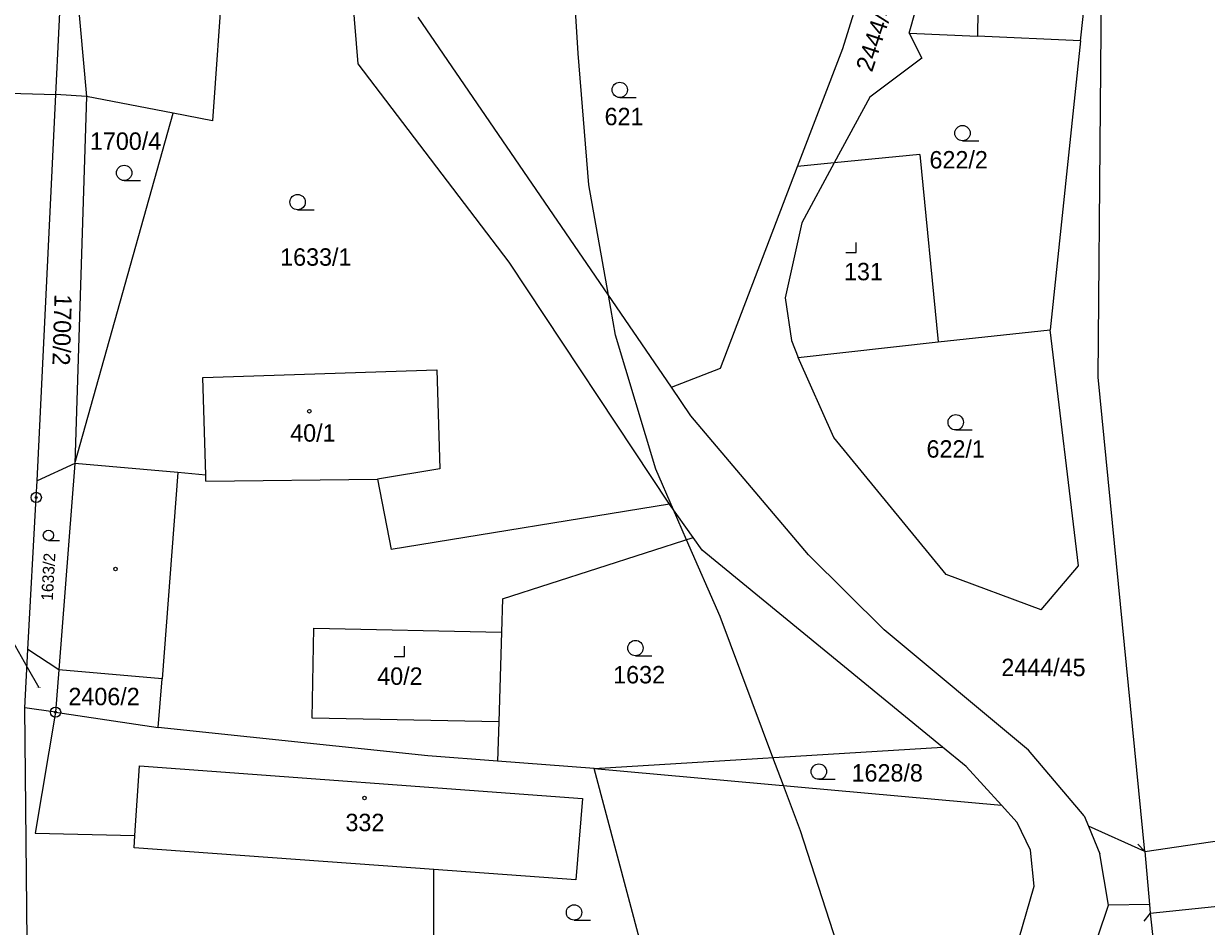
# Model space of a CAD drawing. Extents: x -546762 to -540209, y -1046851 to -1035694.
# Drawn here: x -542720.2 to -542604.8, y -1039556.7 to -1039468.6 of the extents above; entities that cross this region are included whole.
import ezdxf

# ---------------------------------------------------------------- set-up
doc = ezdxf.new("R2010")
doc.units = 0
for name, color, linetype in [('Vrstva 1', 7, 'Continuous'), ('Vrstva 16', 7, 'Continuous'), ('Vrstva 18', 7, 'Continuous'), ('Vrstva 19', 7, 'Continuous'), ('Vrstva 24', 7, 'Continuous'), ('Vrstva 25', 7, 'Continuous'), ('Vrstva 26', 7, 'Continuous'), ('Vrstva 3', 7, 'Continuous'), ('Vrstva 37', 7, 'Continuous'), ('Vrstva 4', 7, 'Continuous'), ('Vrstva 52', 7, 'Continuous')]:
    doc.layers.add(name, color=color, linetype=linetype)

msp = doc.modelspace()

# ---------------------------------------------------------------- linework, layer by layer
at = {"layer": 'Vrstva 1'}
for p, q in [((-542722.87, -1039475.34), (-542717.07, -1039475.49)), ((-542709.35, -1039547.82), (-542708.92, -1039541.01)), ((-542708.92, -1039541.01), (-542665.7, -1039544.19)), ((-542665.7, -1039544.19), (-542666.34, -1039552.15)), ((-542719.1, -1039547.6), (-542709.35, -1039547.82)), ((-542709.43, -1039549), (-542709.35, -1039547.82)), ((-542680.19, -1039551.14), (-542709.43, -1039549)), ((-542666.34, -1039552.15), (-542680.19, -1039551.14)), ((-542680.18, -1039565.65), (-542680.19, -1039551.14))]:
    msp.add_line(p, q, dxfattribs=at)
for points in [[(-542717.07, -1039475.49), (-542715.32, -1039439.55)], [(-542617.09, -1039470.26), (-542614.93, -1039450.36)], [(-542615.38, -1039503.08), (-542614.93, -1039450.36)], [(-542640.3, -1039471), (-542634.14, -1039451.25)], [(-542633.83, -1039469.51), (-542629.48, -1039454.22)], [(-542715.32, -1039461.95), (-542714.08, -1039475.68)], [(-542687.58, -1039472.52), (-542688.45, -1039461.79)], [(-542700.78, -1039463.8), (-542701.79, -1039478.07)], [(-542657.01, -1039504.05), (-542681.72, -1039467.97)], [(-542627.13, -1039467.29), (-542627.16, -1039469.81)], [(-542633.83, -1039469.51), (-542627.16, -1039469.81)], [(-542633.83, -1039469.51), (-542632.58, -1039471.94)], [(-542617.09, -1039470.26), (-542627.16, -1039469.81)], [(-542617.09, -1039470.26), (-542620.05, -1039498.46)], [(-542644.7, -1039482.52), (-542640.3, -1039471)], [(-542672.85, -1039491.86), (-542687.58, -1039472.52)], [(-542632.58, -1039471.94), (-542637.65, -1039475.75)], [(-542718.9, -1039513.21), (-542717.07, -1039475.49)], [(-542714.08, -1039475.68), (-542717.07, -1039475.49)], [(-542714.08, -1039475.68), (-542715.23, -1039511.5)], [(-542705.63, -1039477.32), (-542714.08, -1039475.68)], [(-542637.65, -1039475.75), (-542641.13, -1039482.17)], [(-542715.23, -1039511.5), (-542705.63, -1039477.32)], [(-542701.79, -1039478.07), (-542705.63, -1039477.32)], [(-542632.77, -1039481.35), (-542641.13, -1039482.17)], [(-542632.77, -1039481.35), (-542630.98, -1039499.65)], [(-542652.21, -1039502.21), (-542644.7, -1039482.52)], [(-542641.13, -1039482.17), (-542644.7, -1039482.52)], [(-542641.13, -1039482.17), (-542644.29, -1039488.01)], [(-542644.29, -1039488.01), (-542645.91, -1039495.33)], [(-542657.19, -1039515.49), (-542672.85, -1039491.86)], [(-542645.91, -1039495.33), (-542645.31, -1039499.5)], [(-542630.98, -1039499.65), (-542620.05, -1039498.46)], [(-542617.28, -1039521.5), (-542620.05, -1039498.46)], [(-542645.31, -1039499.5), (-542644.63, -1039501.15)], [(-542644.63, -1039501.15), (-542630.98, -1039499.65)], [(-542641.16, -1039508.96), (-542644.63, -1039501.15)], [(-542702.74, -1039503.11), (-542679.9, -1039502.38)], [(-542679.9, -1039502.38), (-542679.59, -1039512.04)], [(-542657.01, -1039504.05), (-542652.21, -1039502.21)], [(-542702.44, -1039512.64), (-542702.74, -1039503.11)], [(-542610.81, -1039549.38), (-542615.38, -1039503.08)], [(-542655.1, -1039506.86), (-542657.01, -1039504.05)], [(-542643.62, -1039520.41), (-542655.1, -1039506.86)], [(-542630.21, -1039522.33), (-542641.16, -1039508.96)], [(-542715.23, -1039511.5), (-542718.9, -1039513.21)], [(-542715.23, -1039511.5), (-542716.77, -1039531.63)], [(-542705.17, -1039512.4), (-542715.23, -1039511.5)], [(-542702.44, -1039512.64), (-542705.17, -1039512.4)], [(-542679.59, -1039512.04), (-542685.69, -1039513.03)], [(-542718.98, -1039514.82), (-542718.9, -1039513.21)], [(-542685.69, -1039513.03), (-542684.34, -1039519.91)], [(-542719.79, -1039529.65), (-542718.98, -1039514.82)], [(-542657.19, -1039515.49), (-542684.34, -1039519.91)], [(-542654.88, -1039518.74), (-542657.19, -1039515.49)], [(-542673.49, -1039524.73), (-542654.88, -1039518.74)], [(-542654, -1039519.97), (-542654.88, -1039518.74)], [(-542630.56, -1039539.19), (-542654, -1039519.97)], [(-542636.24, -1039527.75), (-542643.62, -1039520.41)], [(-542620.94, -1039525.78), (-542617.28, -1039521.5)], [(-542620.94, -1039525.78), (-542630.21, -1039522.33)], [(-542673.49, -1039524.73), (-542673.59, -1039527.96)], [(-542692.07, -1039536.35), (-542691.89, -1039527.58)], [(-542691.89, -1039527.58), (-542673.59, -1039527.96)], [(-542673.59, -1039527.96), (-542673.86, -1039536.73)], [(-542622.16, -1039539.49), (-542636.24, -1039527.75)], [(-542720.1, -1039535.34), (-542719.79, -1039529.65)], [(-542716.77, -1039531.63), (-542719.79, -1039529.65)], [(-542716.77, -1039531.63), (-542717.09, -1039535.78)], [(-542706.71, -1039532.53), (-542716.77, -1039531.63)], [(-542707.08, -1039537.27), (-542706.71, -1039532.53)], [(-542719.28, -1039616.7), (-542720.1, -1039535.34)], [(-542717.09, -1039535.78), (-542720.1, -1039535.34)], [(-542717.09, -1039535.78), (-542719.1, -1039547.6)], [(-542717.09, -1039535.78), (-542707.08, -1039537.27)], [(-542673.86, -1039536.73), (-542692.07, -1039536.35)], [(-542673.86, -1039536.73), (-542673.98, -1039540.56)], [(-542680.77, -1039540.05), (-542707.08, -1039537.27)], [(-542664.56, -1039541.27), (-542630.56, -1039539.19)], [(-542628.26, -1039541.08), (-542630.56, -1039539.19)], [(-542616.75, -1039545.89), (-542622.16, -1039539.49)], [(-542673.98, -1039540.56), (-542680.77, -1039540.05)], [(-542664.56, -1039541.27), (-542673.98, -1039540.56)], [(-542657.86, -1039566.46), (-542664.56, -1039541.27)], [(-542664.56, -1039541.27), (-542624.82, -1039544.85)], [(-542624.82, -1039544.85), (-542628.26, -1039541.08)], [(-542623.28, -1039546.55), (-542624.82, -1039544.85)], [(-542616.75, -1039545.89), (-542616.33, -1039546.91)], [(-542621.98, -1039549.25), (-542623.28, -1039546.55)], [(-542610.81, -1039549.38), (-542616.33, -1039546.91)], [(-542616.33, -1039546.91), (-542615.21, -1039549.6)], [(-542610.81, -1039549.38), (-542601.31, -1039547.99)], [(-542621.62, -1039552.75), (-542621.98, -1039549.25)], [(-542614.37, -1039554.62), (-542615.21, -1039549.6)], [(-542624.18, -1039561.65), (-542621.62, -1039552.75)], [(-542610.36, -1039554.53), (-542614.37, -1039554.62)], [(-542610.36, -1039554.53), (-542610.29, -1039555.38)], [(-542610.29, -1039555.38), (-542600.59, -1039554.38)], [(-542615.4, -1039557.71), (-542614.37, -1039554.62)], [(-542610.29, -1039555.38), (-542606.95, -1039585.89)]]:
    msp.add_lwpolyline(points, dxfattribs=at)
at = {"layer": 'Vrstva 16'}
msp.add_line((-542719.83, -1039531.42), (-542721.31, -1039528.81), dxfattribs=at)
msp.add_lwpolyline([(-542718.71, -1039533.41), (-542719.83, -1039531.42)], dxfattribs=at)
at = {"layer": 'Vrstva 24'}
for centre, radius in [((-542718.98, -1039514.82), 0.5), ((-542718.98, -1039514.82), 0.1), ((-542717.09, -1039535.78), 0.5), ((-542717.09, -1039535.78), 0.1)]:
    msp.add_circle(centre, radius, dxfattribs=at)
at = {"layer": 'Vrstva 25'}
for p, q in [((-542662.05, -1039475.8), (-542660.45, -1039475.8)), ((-542628.61, -1039480.02), (-542627.01, -1039480.02)), ((-542710.4, -1039483.9), (-542708.8, -1039483.9)), ((-542693.48, -1039486.75), (-542691.88, -1039486.75)), ((-542629.27, -1039508.24), (-542627.67, -1039508.24)), ((-542717.79, -1039519.02), (-542716.72, -1039519.02)), ((-542660.52, -1039530.27), (-542658.92, -1039530.27)), ((-542642.63, -1039542.33), (-542641.03, -1039542.33)), ((-542666.51, -1039556.07), (-542664.91, -1039556.07))]:
    msp.add_line(p, q, dxfattribs=at)
for points in [[(-542639.98, -1039490.93), (-542638.98, -1039490.93), (-542638.98, -1039489.93)], [(-542684.05, -1039530.34), (-542683.05, -1039530.34), (-542683.05, -1039529.34)]]:
    msp.add_lwpolyline(points, dxfattribs=at)
for centre, radius in [((-542662.05, -1039475.05), 0.75), ((-542628.61, -1039479.27), 0.75), ((-542710.4, -1039483.15), 0.75), ((-542693.48, -1039486), 0.75), ((-542692.33, -1039506.41), 0.175), ((-542629.27, -1039507.49), 0.75), ((-542717.79, -1039518.52), 0.503), ((-542711.25, -1039521.8), 0.175), ((-542660.52, -1039529.52), 0.75), ((-542642.63, -1039541.58), 0.75), ((-542686.95, -1039544.15), 0.175), ((-542666.51, -1039555.32), 0.75)]:
    msp.add_circle(centre, radius, dxfattribs=at)
at = {"layer": 'Vrstva 26'}
for p, q in [((-542610.81, -1039549.38), (-542611.51, -1039548.66)), ((-542610.29, -1039555.38), (-542610.92, -1039556.16))]:
    msp.add_line(p, q, dxfattribs=at)
at = {"layer": 'Vrstva 3'}
for points in [[(-542702.74, -1039503.11), (-542679.9, -1039502.38)], [(-542679.9, -1039502.38), (-542679.59, -1039512.04)], [(-542702.44, -1039512.64), (-542702.74, -1039503.11)], [(-542702.42, -1039513.23), (-542702.44, -1039512.64)], [(-542679.59, -1039512.04), (-542685.69, -1039513.03)], [(-542702.42, -1039513.23), (-542685.69, -1039513.03)], [(-542709.35, -1039547.82), (-542708.92, -1039541.01)], [(-542708.92, -1039541.01), (-542665.7, -1039544.19)], [(-542665.7, -1039544.19), (-542666.34, -1039552.15)], [(-542709.43, -1039549), (-542709.35, -1039547.82)], [(-542680.19, -1039551.14), (-542709.43, -1039549)], [(-542666.34, -1039552.15), (-542680.19, -1039551.14)]]:
    msp.add_lwpolyline(points, dxfattribs=at)
at = {"layer": 'Vrstva 37'}
for centre in [(-542692.33, -1039506.41), (-542686.95, -1039544.15)]:
    msp.add_circle(centre, 0.175, dxfattribs=at)
at = {"layer": 'Vrstva 4'}
for points in [[(-542705.17, -1039512.4), (-542706.71, -1039532.53)], [(-542702.42, -1039513.23), (-542702.44, -1039512.64)], [(-542702.42, -1039513.23), (-542685.69, -1039513.03)], [(-542610.81, -1039549.38), (-542610.36, -1039554.53)]]:
    msp.add_lwpolyline(points, dxfattribs=at)
at = {"layer": 'Vrstva 52'}
msp.add_lwpolyline([(-542635.54, -1039574.82), (-542644.42, -1039547.36), (-542646.08, -1039542.93), (-542647.1, -1039540.2), (-542652.26, -1039526.44), (-542655.53, -1039518.95), (-542656.8, -1039516.04), (-542658.54, -1039512.05), (-542662.46, -1039498.98), (-542663.16, -1039495.08), (-542665.07, -1039484.33), (-542666.12, -1039471.51), (-542666.87, -1039459.43)], dxfattribs=at)

# ---------------------------------------------------------------- texts
at = {"layer": 'Vrstva 18'}
for s, height, rotation, p in [('2444/47', 1.7, 71.7549, (-542637.44, -1039473.39)), ('1700/2', 1.7, 268.2404, (-542717.19, -1039494.97)), ('1633/2', 1.14, 86.7425, (-542717.37, -1039524.93))]:
    msp.add_text(s, height=height, rotation=rotation, dxfattribs=at).set_placement(p)
for s, height, p in [('621', 1.7, (-542663.53, -1039478.5)), ('1700/4', 1.7, (-542713.74, -1039480.9)), ('622/2', 1.7, (-542631.83, -1039482.72)), ('1633/1', 1.7, (-542695.18, -1039492.21)), ('622/1', 1.7, (-542632.12, -1039510.94)), ('1632', 1.7, (-542662.69, -1039532.97)), ('2444/45', 1.7, (-542624.82, -1039532.26)), ('2406/3', 0.1, (-542718.94, -1039533.41)), ('2406/2', 1.7, (-542715.84, -1039535.1)), ('1628/8', 1.7, (-542639.43, -1039542.55))]:
    msp.add_text(s, height=height, dxfattribs=at).set_placement(p)
at = {"layer": 'Vrstva 19'}
for s, p in [('131', (-542640.17, -1039493.63)), ('40/1', (-542694.2, -1039509.38)), ('40/2', (-542685.71, -1039533.11)), ('332', (-542688.81, -1039547.39))]:
    msp.add_text(s, height=1.7, dxfattribs=at).set_placement(p)

doc.saveas('drawing.dxf')
